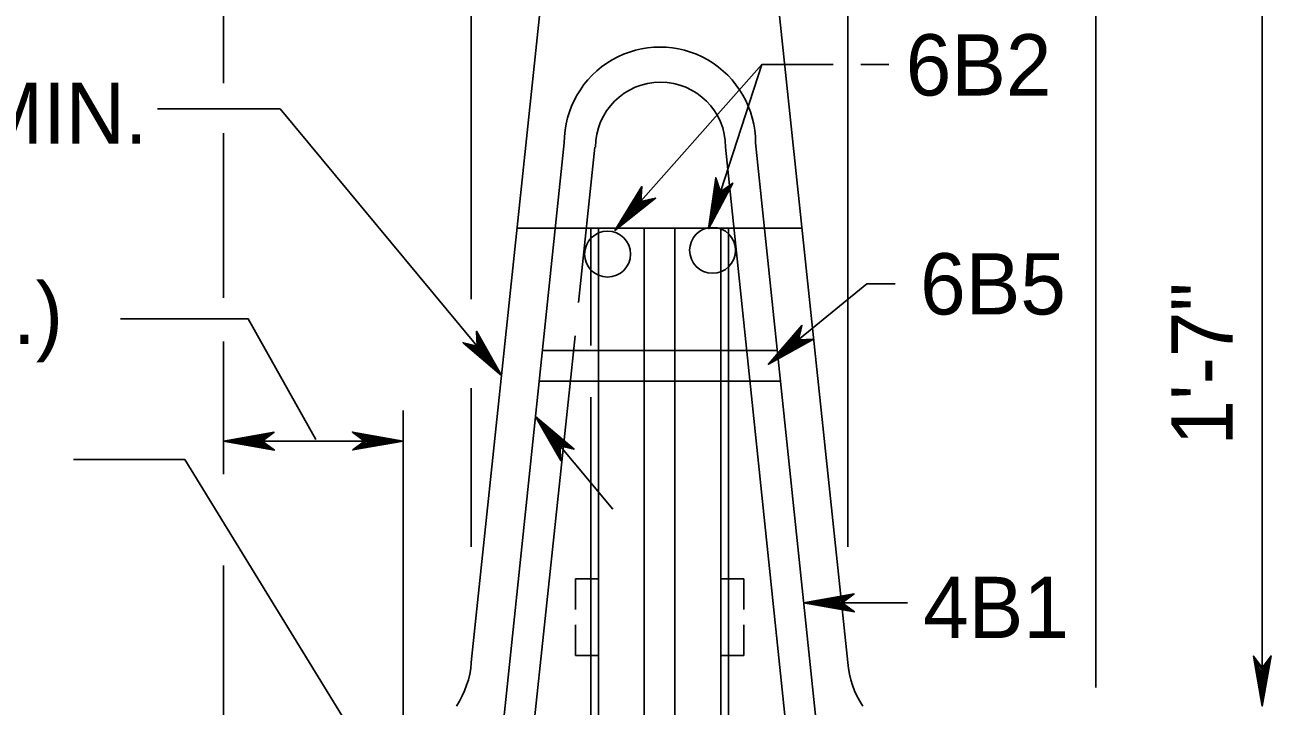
# Model space of a CAD drawing. Extents: x 499883 to 500983, y 499104 to 499764.
# Drawn here: x 500323 to 500404.4, y 499478 to 499522.4 of the extents above; entities that cross this region are included whole.
import ezdxf

# ---------------------------------------------------------------- set-up
doc = ezdxf.new("R2010")
doc.units = 0
for name, color, linetype in [('24', 7, 'Continuous'), ('5', 7, 'Continuous'), ('60', 7, 'Continuous')]:
    doc.layers.add(name, color=color, linetype=linetype)

msp = doc.modelspace()

# ---------------------------------------------------------------- linework, layer by layer
at = {"layer": '24'}
for points in [[(500371.584, 499500.277), (500378.019, 499505.536), (500379.859, 499505.536)], [(500354.165, 499499.543), (500352.517, 499502.431), (500352.572, 499501.459), (500351.644, 499501.683), (500354.165, 499499.543), (500354.021, 499499.707), (500352.542, 499502.333), (500352.605, 499501.408), (500351.764, 499501.61), (500353.938, 499499.79), (500353.881, 499499.884), (500352.605, 499502.126), (500352.617, 499501.395), (500351.9, 499501.561), (500353.849, 499499.923), (500353.767, 499499.996), (500352.656, 499501.959), (500352.637, 499501.382), (500352.048, 499501.465), (500353.565, 499500.239), (500353.447, 499500.381), (500352.698, 499501.78), (500352.666, 499501.36), (500352.208, 499501.402), (500353.438, 499500.417), (500353.334, 499500.558), (500352.741, 499501.584), (500352.71, 499501.267), (500352.383, 499501.311), (500353.224, 499500.675), (500353.131, 499500.812), (500352.786, 499501.438), (500352.739, 499501.248), (500352.482, 499501.283), (500353.064, 499500.868), (500352.855, 499501.289), (500352.801, 499501.158), (500352.576, 499501.232), (500352.977, 499500.945), (500352.843, 499501.225), (500352.848, 499501.064), (500352.71, 499501.138), (500352.873, 499501.086), (500352.837, 499501.154)], [(500371.584, 499500.277), (500374.529, 499501.925), (500373.542, 499501.878), (500373.778, 499502.817), (500371.584, 499500.277), (500371.751, 499500.422), (500374.43, 499501.9), (500373.49, 499501.844), (500373.703, 499502.697), (500371.836, 499500.505), (500371.933, 499500.563), (500374.219, 499501.839), (500373.477, 499501.833), (500373.652, 499502.559), (500371.972, 499500.594), (500372.047, 499500.677), (500374.05, 499501.788), (500373.463, 499501.813), (500373.553, 499502.41), (500372.295, 499500.88), (500372.44, 499500.999), (500373.867, 499501.748), (500373.441, 499501.783), (500373.488, 499502.248), (500372.477, 499501.007), (500372.621, 499501.112), (500373.668, 499501.705), (500373.346, 499501.739), (500373.393, 499502.072), (500372.741, 499501.223), (500372.881, 499501.315), (500373.519, 499501.661), (500373.327, 499501.711), (500373.365, 499501.971), (500372.938, 499501.383), (500373.367, 499501.592), (500373.235, 499501.648), (500373.312, 499501.876), (500373.017, 499501.471), (500373.302, 499501.604), (500373.139, 499501.601), (500373.215, 499501.741), (500373.161, 499501.576), (500373.231, 499501.611)], [(500356.379, 499496.881), (500358.027, 499493.994), (500357.972, 499494.965), (500358.899, 499494.74), (500356.379, 499496.881), (500356.522, 499496.717), (500358.001, 499494.091), (500357.938, 499495.016), (500358.78, 499494.813), (500356.605, 499496.634), (500356.662, 499496.54), (500357.939, 499494.298), (500357.927, 499495.029), (500358.643, 499494.863), (500356.694, 499496.501), (500356.776, 499496.428), (500357.887, 499494.465), (500357.907, 499495.042), (500358.496, 499494.959), (500356.979, 499496.185), (500357.096, 499496.043), (500357.846, 499494.644), (500357.877, 499495.063), (500358.336, 499495.021), (500357.105, 499496.007), (500357.209, 499495.866), (500357.802, 499494.839), (500357.833, 499495.157), (500358.161, 499495.113), (500357.32, 499495.75), (500357.412, 499495.612), (500357.758, 499494.986), (500357.805, 499495.176), (500358.062, 499495.141), (500357.479, 499495.557), (500357.688, 499495.135), (500357.743, 499495.266), (500357.967, 499495.191), (500357.566, 499495.479), (500357.7, 499495.199), (500357.696, 499495.36), (500357.833, 499495.286), (500357.671, 499495.338), (500357.706, 499495.27)], [(500403.834, 499477.975), (500404.412, 499481.249), (500403.834, 499480.467), (500403.264, 499481.232), (500403.834, 499477.975), (500403.828, 499478.192), (500404.37, 499481.157), (500403.827, 499480.406), (500403.309, 499481.1), (500403.818, 499478.31), (500403.834, 499478.419), (500404.285, 499480.959), (500403.827, 499480.389), (500403.383, 499480.975), (500403.834, 499478.469), (500403.818, 499478.577), (500404.218, 499480.797), (500403.834, 499480.366), (500403.434, 499480.807), (500403.817, 499478.894), (500403.818, 499479.078), (500404.136, 499480.633), (500403.843, 499480.331), (500403.517, 499480.656), (500403.834, 499479.111), (500403.844, 499479.286), (500404.044, 499480.455), (500403.817, 499480.23), (500403.593, 499480.474), (500403.834, 499479.447), (500403.85, 499479.612), (500403.985, 499480.313), (500403.827, 499480.198), (500403.652, 499480.389), (500403.834, 499479.697), (500403.943, 499480.155), (500403.818, 499480.089), (500403.692, 499480.29), (500403.817, 499479.813), (500403.892, 499480.113), (500403.794, 499479.987), (500403.735, 499480.131), (500403.827, 499479.988), (500403.843, 499480.063)]]:
    msp.add_lwpolyline(points, dxfattribs=at)
at = {"layer": '5'}
for p, q in [((500336.003, 499518.618), (500336.003, 499537.135)), ((500352.184, 499504.527), (500352.184, 499537.135)), ((500403.834, 499477.975), (500403.834, 499526.242)), ((500356.882, 499525.249), (500352.184, 499480.807)), ((500372.082, 499525.249), (500376.779, 499480.807)), ((500376.779, 499488.362), (500376.779, 499524.904)), ((500392.96, 499479.188), (500392.96, 499525.057)), ((500371.165, 499519.831), (500361.568, 499509.019)), ((500371.165, 499519.831), (500367.67, 499509.126)), ((500375.806, 499519.831), (500371.165, 499519.831)), ((500379.457, 499519.831), (500377.625, 499519.831)), ((500336.003, 499504.604), (500336.003, 499515.368)), ((500358.258, 499514.732), (500352.017, 499455.451)), ((500370.749, 499514.732), (500376.902, 499455.918)), ((500360.261, 499514.445), (500359.19, 499504.304)), ((500368.792, 499514.441), (500374.899, 499455.866)), ((500355.178, 499509.168), (500373.795, 499509.168)), ((500359.985, 499509.168), (500359.985, 499501.498)), ((500359.985, 499509.168), (500359.985, 499501.498)), ((500360.485, 499509.168), (500360.485, 499459.293)), ((500363.483, 499509.168), (500363.483, 499459.293)), ((500365.481, 499509.199), (500365.481, 499459.293)), ((500368.479, 499509.199), (500368.479, 499459.293)), ((500368.978, 499509.199), (500368.978, 499459.293)), ((500336.003, 499493.102), (500336.003, 499501.76)), ((500358.961, 499502.138), (500358.588, 499498.613)), ((500356.79, 499501.174), (500360.485, 499501.174)), ((500360.485, 499501.174), (500368.479, 499501.174)), ((500368.479, 499501.174), (500372.137, 499501.174)), ((500356.589, 499499.175), (500360.485, 499499.175)), ((500360.485, 499499.175), (500368.479, 499499.175)), ((500368.479, 499499.175), (500372.338, 499499.175)), ((500352.184, 499488.362), (500352.184, 499498.709)), ((500352.184, 499488.362), (500352.184, 499498.709)), ((500358.61, 499498.82), (500354.029, 499455.472)), ((500359.985, 499498.127), (500359.985, 499459.293)), ((500347.745, 499444.305), (500347.745, 499497.261)), ((500356.379, 499496.881), (500361.423, 499490.813)), ((500347.745, 499495.263), (500336.003, 499495.263)), ((500336.003, 499459.079), (500336.003, 499487.137)), ((500358.986, 499486.272), (500358.986, 499484.274)), ((500358.986, 499486.272), (500360.485, 499486.272)), ((500368.479, 499486.272), (500369.977, 499486.272)), ((500369.977, 499486.272), (500369.977, 499484.274)), ((500380.662, 499484.72), (500373.879, 499484.72)), ((500358.986, 499481.276), (500358.986, 499483.274)), ((500369.977, 499481.276), (500369.977, 499483.274)), ((500358.986, 499481.276), (500360.485, 499481.276)), ((500368.479, 499481.276), (500369.977, 499481.276))]:
    msp.add_line(p, q, dxfattribs=at)
for points in [[(500331.701, 499516.944), (500339.698, 499516.944), (500354.165, 499499.543)], [(500367.67, 499509.126), (500369.26, 499512.103), (500368.455, 499511.531), (500368.146, 499512.449), (500367.67, 499509.126), (500367.733, 499509.338), (500369.19, 499512.028), (500368.429, 499511.474), (500368.148, 499512.307), (500367.76, 499509.454), (500367.81, 499509.555), (500369.046, 499511.863), (500368.424, 499511.458), (500368.18, 499512.163), (500367.826, 499509.603), (500367.844, 499509.712), (500368.931, 499511.729), (500368.424, 499511.433), (500368.177, 499511.984), (500367.944, 499510.018), (500368.002, 499510.196), (500368.799, 499511.596), (500368.421, 499511.396), (500368.21, 499511.813), (500368.028, 499510.223), (500368.093, 499510.388), (500368.654, 499511.453), (500368.365, 499511.308), (500368.225, 499511.614), (500368.134, 499510.546), (500368.202, 499510.701), (500368.552, 499511.335), (500368.364, 499511.274), (500368.255, 499511.514), (500368.213, 499510.788), (500368.462, 499511.195), (500368.32, 499511.171), (500368.263, 499511.404), (500368.233, 499510.904), (500368.4, 499511.171), (500368.265, 499511.081), (500368.253, 499511.238), (500368.297, 499511.071), (500368.337, 499511.138)], [(500361.568, 499509.019), (500364.214, 499511.115), (500363.248, 499510.911), (500363.331, 499511.876), (500361.568, 499509.019), (500361.71, 499509.188), (500364.12, 499511.074), (500363.201, 499510.869), (500363.276, 499511.745), (500361.782, 499509.284), (500361.868, 499509.356), (500363.922, 499510.98), (500363.19, 499510.856), (500363.247, 499511.601), (500361.901, 499509.394), (500361.962, 499509.487), (500363.763, 499510.903), (500363.18, 499510.834), (500363.174, 499511.438), (500362.175, 499509.728), (500362.3, 499509.868), (500363.589, 499510.834), (500363.163, 499510.801), (500363.135, 499511.268), (500362.334, 499509.882), (500362.46, 499510.008), (500363.399, 499510.76), (500363.076, 499510.743), (500363.07, 499511.079), (500362.56, 499510.136), (500362.684, 499510.25), (500363.259, 499510.693), (500363.061, 499510.711), (500363.058, 499510.975), (500362.729, 499510.327), (500363.12, 499510.601), (500362.981, 499510.635), (500363.021, 499510.872), (500362.794, 499510.425), (500363.054, 499510.603), (500362.894, 499510.574), (500362.946, 499510.723), (500362.919, 499510.552), (500362.983, 499510.598)], [(500329.266, 499503.235), (500337.622, 499503.235), (500342.021, 499495.36)], [(500336.003, 499495.263), (500339.327, 499494.675), (500338.533, 499495.263), (500339.31, 499495.841), (500336.003, 499495.263), (500336.224, 499495.269), (500339.234, 499494.719), (500338.471, 499495.27), (500339.176, 499495.795), (500336.343, 499495.279), (500336.454, 499495.263), (500339.033, 499494.805), (500338.454, 499495.27), (500339.049, 499495.721), (500336.505, 499495.263), (500336.615, 499495.279), (500338.869, 499494.873), (500338.431, 499495.263), (500338.878, 499495.668), (500336.936, 499495.28), (500337.123, 499495.279), (500338.702, 499494.956), (500338.395, 499495.253), (500338.725, 499495.584), (500337.157, 499495.263), (500337.334, 499495.252), (500338.521, 499495.049), (500338.293, 499495.28), (500338.54, 499495.507), (500337.497, 499495.263), (500337.665, 499495.246), (500338.377, 499495.11), (500338.26, 499495.27), (500338.454, 499495.447), (500337.752, 499495.262), (500338.216, 499495.152), (500338.149, 499495.279), (500338.353, 499495.407), (500337.869, 499495.28), (500338.174, 499495.203), (500338.046, 499495.304), (500338.192, 499495.364), (500338.047, 499495.27), (500338.123, 499495.253)], [(500347.745, 499495.263), (500344.42, 499495.851), (500345.214, 499495.263), (500344.438, 499494.685), (500347.745, 499495.263), (500347.523, 499495.256), (500344.514, 499495.807), (500345.277, 499495.256), (500344.572, 499494.73), (500347.405, 499495.247), (500347.294, 499495.263), (500344.715, 499495.721), (500345.294, 499495.256), (500344.699, 499494.805), (500347.243, 499495.263), (500347.133, 499495.247), (500344.879, 499495.653), (500345.317, 499495.263), (500344.87, 499494.858), (500346.812, 499495.246), (500346.624, 499495.246), (500345.046, 499495.569), (500345.353, 499495.272), (500345.022, 499494.941), (500346.591, 499495.263), (500346.413, 499495.273), (500345.227, 499495.476), (500345.454, 499495.246), (500345.207, 499495.018), (500346.25, 499495.263), (500346.082, 499495.28), (500345.37, 499495.416), (500345.488, 499495.256), (500345.293, 499495.078), (500345.996, 499495.263), (500345.531, 499495.374), (500345.598, 499495.246), (500345.394, 499495.119), (500345.879, 499495.246), (500345.574, 499495.322), (500345.702, 499495.222), (500345.556, 499495.162), (500345.701, 499495.256), (500345.625, 499495.272)], [(500326.216, 499494.065), (500333.475, 499494.065), (500347.528, 499471.164)], [(500373.879, 499484.72), (500377.202, 499484.132), (500376.408, 499484.72), (500377.185, 499485.298), (500373.879, 499484.72), (500374.099, 499484.726), (500377.109, 499484.176), (500376.346, 499484.727), (500377.051, 499485.252), (500374.218, 499484.736), (500374.329, 499484.72), (500376.907, 499484.262), (500376.329, 499484.727), (500376.924, 499485.178), (500374.38, 499484.72), (500374.49, 499484.736), (500376.744, 499484.33), (500376.306, 499484.72), (500376.753, 499485.125), (500374.811, 499484.737), (500374.999, 499484.736), (500376.577, 499484.414), (500376.27, 499484.71), (500376.6, 499485.041), (500375.032, 499484.72), (500375.21, 499484.709), (500376.396, 499484.506), (500376.168, 499484.737), (500376.415, 499484.964), (500375.373, 499484.72), (500375.54, 499484.703), (500376.253, 499484.567), (500376.135, 499484.727), (500376.329, 499484.904), (500375.627, 499484.719), (500376.092, 499484.609), (500376.025, 499484.736), (500376.229, 499484.864), (500375.744, 499484.737), (500376.049, 499484.66), (500375.921, 499484.761), (500376.068, 499484.821), (500375.922, 499484.727), (500375.998, 499484.71)]]:
    msp.add_lwpolyline(points, dxfattribs=at)
for centre, radius, start, end in [((500364.503, 499514.732), 6.245, 359.93421, 180.02301), ((500364.545, 499514.441), 4.247, 0, 180), ((500346.207, 499481.265), 5.995, 326.72496, 355.62643), ((500382.757, 499481.265), 5.995, 184.37357, 213.27504)]:
    msp.add_arc(centre, radius, start, end, dxfattribs=at)
at = {"layer": '60'}
for centre in [(500361.08, 499507.465), (500367.938, 499507.715)]:
    msp.add_circle(centre, 1.499, dxfattribs=at)

# ---------------------------------------------------------------- texts
at = {"layer": '5'}
for s, p in [('6B2', (500380.554, 499517.817)), ('1 1/2" COV. MIN.', (500289.912, 499514.666)), ('6B5', (500381.495, 499503.527)), ('5 3/4" (TYP.)', (500294.789, 499501.6)), ('4B1', (500381.69, 499482.412))]:
    msp.add_text(s, height=4, dxfattribs=at).set_placement(p)
msp.add_text('1\'-7"', height=4, rotation=90, dxfattribs=at).set_placement((500401.897, 499494.973))

doc.saveas('drawing.dxf')
